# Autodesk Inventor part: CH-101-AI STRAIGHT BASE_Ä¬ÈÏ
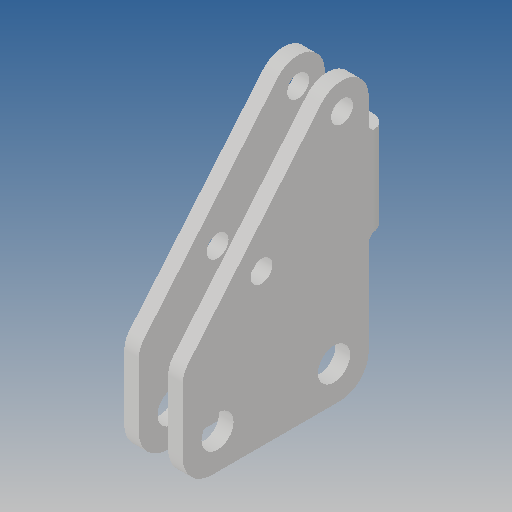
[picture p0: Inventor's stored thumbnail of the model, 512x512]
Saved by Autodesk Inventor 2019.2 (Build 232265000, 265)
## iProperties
Created: 2010-06
Part Number: CH-101-AI STRAIGHT BASE_Ä¬ÈÏ
Material: Ogólny
Document SubType Name: Modeling
Designer: CADENGINEERING4
Density: 1 g/cm^3
Appearance: Domyślna
Author: CADENGINEERING4
Revision Number: ÈÎºÎ
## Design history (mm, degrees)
feature "NONE"
node "Bryła1"
